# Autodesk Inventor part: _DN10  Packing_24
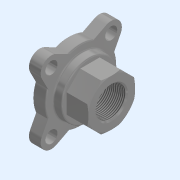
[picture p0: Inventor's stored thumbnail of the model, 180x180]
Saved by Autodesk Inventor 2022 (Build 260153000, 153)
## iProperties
Created: 2021-12
Part Number: _DN10  Packing_24
Material: Generico
Document SubType Name: Modeling
Designer: admin
Density: 1 g/cm^3
Appearance: Default
Author: admin
Revision Number: NONE
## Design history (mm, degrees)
feature "_DN10  Packing"
feature "Filettatura1" dims "d0" = 15, "d1" = 0
node "Solido1"
